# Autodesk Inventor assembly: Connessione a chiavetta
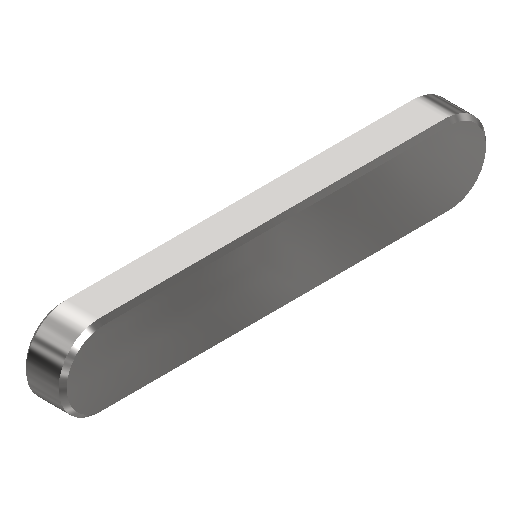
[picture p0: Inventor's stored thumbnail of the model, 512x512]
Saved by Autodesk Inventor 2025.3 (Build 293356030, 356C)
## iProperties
ClientObjectVersion: 1
Created: 2026-05
Part Number: Connessione a chiavetta
Document SubType Name: Assembly
Designer: R5800u
Author: R5800u
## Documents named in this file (2)
- C:\Users\R5800u\Desktop\riduttore pompa - Copia\riduttore2\Design Accelerator\Connessione a chiavetta4.iam
- C:\Users\R5800u\Documents\Inventor\Content Center Files\R2025\it-IT\ISO 2491 - A\ISO 2491 - A  12 x 6 x 63.ipt
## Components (1 placed, 1 different names)
1. ISO 2491 A A  12 x 6 x 63:1
